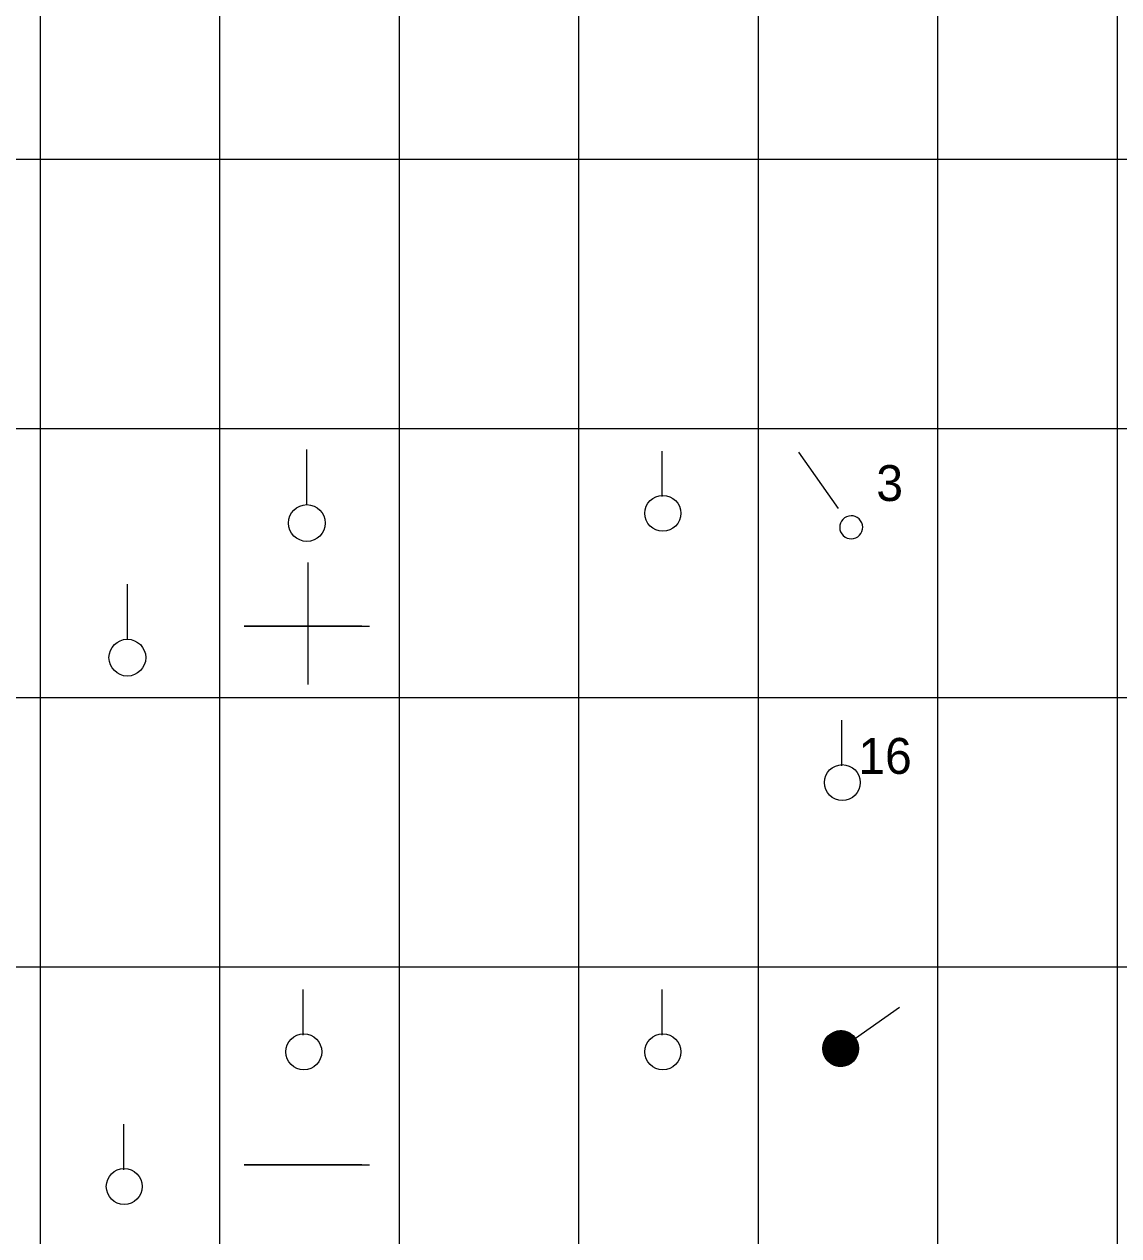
# Model space of a CAD drawing. Extents: x -28 to 822, y 61 to 665.
# Drawn here: x 399.7 to 460.7, y 246.8 to 314.2 of the extents above; entities that cross this region are included whole.
import ezdxf

# ---------------------------------------------------------------- set-up
doc = ezdxf.new("R2010")
doc.units = 0
doc.layers.add('KOLEJIŠTĚ', color=7, linetype='Continuous')

# ---------------------------------------------------------------- blocks, each defined once
blk = doc.blocks.new('_X10')
for p, q in [((370.452, 480.16), (371.464, 481.172)), ((370.452, 480.177), (371.447, 481.172)), ((370.452, 480.195), (371.429, 481.172)), ((370.453, 480.142), (371.482, 481.172)), ((370.453, 480.125), (371.499, 481.171)), ((370.453, 480.214), (371.411, 481.171)), ((370.454, 480.109), (371.515, 481.17)), ((370.454, 480.232), (371.392, 481.17)), ((370.455, 480.092), (371.532, 481.169)), ((370.455, 480.251), (371.373, 481.169)), ((370.457, 480.076), (371.548, 481.167)), ((370.457, 480.271), (371.353, 481.167)), ((370.458, 480.06), (371.564, 481.166)), ((370.459, 480.291), (371.334, 481.165)), ((370.46, 480.044), (371.58, 481.164)), ((370.462, 480.029), (371.596, 481.162)), ((370.462, 480.311), (371.313, 481.162)), ((370.465, 480.013), (371.611, 481.159)), ((370.465, 480.332), (371.293, 481.159)), ((370.467, 479.998), (371.626, 481.157)), ((370.469, 480.353), (371.271, 481.156)), ((370.47, 479.983), (371.641, 481.154)), ((370.473, 479.969), (371.656, 481.151)), ((370.473, 480.375), (371.249, 481.151)), ((370.476, 479.954), (371.67, 481.148)), ((370.478, 480.398), (371.227, 481.146)), ((370.479, 479.94), (371.685, 481.145)), ((370.483, 479.925), (371.699, 481.141)), ((370.484, 480.421), (371.203, 481.141)), ((370.487, 479.911), (371.713, 481.137)), ((370.49, 480.445), (371.179, 481.134)), ((370.491, 479.898), (371.727, 481.134)), ((370.495, 479.884), (371.74, 481.13)), ((370.498, 480.47), (371.154, 481.126)), ((370.499, 479.87), (371.754, 481.125)), ((370.503, 479.857), (371.767, 481.121)), ((370.506, 480.497), (371.127, 481.118)), ((370.507, 479.844), (371.78, 481.117)), ((370.512, 479.831), (371.793, 481.112)), ((370.516, 480.524), (371.1, 481.108)), ((370.517, 479.818), (371.806, 481.107)), ((370.522, 479.805), (371.819, 481.102)), ((370.527, 479.793), (371.832, 481.097)), ((370.528, 480.554), (371.071, 481.096)), ((370.532, 479.78), (371.844, 481.092)), ((370.537, 479.768), (371.856, 481.087)), ((370.541, 480.585), (371.039, 481.083)), ((370.543, 479.756), (371.869, 481.081)), ((370.549, 479.744), (371.881, 481.076)), ((370.554, 479.732), (371.893, 481.07)), ((370.557, 480.618), (371.006, 481.067)), ((370.56, 479.72), (371.904, 481.064)), ((370.566, 479.708), (371.916, 481.058)), ((370.572, 479.697), (371.928, 481.052)), ((370.577, 480.656), (370.968, 481.047)), ((370.579, 479.685), (371.939, 481.046)), ((370.585, 479.674), (371.95, 481.039)), ((370.592, 479.663), (371.961, 481.033)), ((370.598, 479.652), (371.972, 481.026)), ((370.602, 480.698), (370.926, 481.022)), ((370.605, 479.641), (371.983, 481.019)), ((370.612, 479.63), (371.994, 481.012)), ((370.619, 479.619), (372.005, 481.005)), ((370.626, 479.609), (372.015, 480.998)), ((370.633, 479.598), (372.026, 480.991)), ((370.637, 480.751), (370.873, 480.988)), ((370.64, 479.588), (372.036, 480.984)), ((370.648, 479.578), (372.046, 480.976)), ((370.655, 479.568), (372.057, 480.969)), ((370.663, 479.558), (372.067, 480.961)), ((370.671, 479.548), (372.076, 480.953)), ((370.679, 479.538), (372.086, 480.945)), ((370.687, 479.528), (372.096, 480.937)), ((370.695, 479.519), (372.105, 480.929)), ((370.703, 479.509), (372.115, 480.921)), ((370.706, 480.838), (370.786, 480.918)), ((370.712, 479.5), (372.124, 480.913)), ((370.72, 479.491), (372.133, 480.904)), ((370.729, 479.482), (372.142, 480.896)), ((370.737, 479.473), (372.151, 480.887)), ((370.746, 479.464), (372.16, 480.878)), ((370.755, 479.455), (372.169, 480.869)), ((370.764, 479.446), (372.178, 480.86)), ((370.773, 479.438), (372.186, 480.851)), ((370.782, 479.429), (372.195, 480.842)), ((370.792, 479.421), (372.203, 480.832)), ((370.801, 479.413), (372.211, 480.823)), ((370.811, 479.405), (372.219, 480.813)), ((370.821, 479.397), (372.227, 480.804)), ((370.83, 479.389), (372.235, 480.794)), ((370.84, 479.381), (372.243, 480.784)), ((370.85, 479.373), (372.251, 480.774)), ((370.86, 479.366), (372.258, 480.764)), ((370.871, 479.358), (372.266, 480.754)), ((370.881, 479.351), (372.273, 480.743)), ((370.891, 479.344), (372.28, 480.733)), ((370.902, 479.337), (372.287, 480.722)), ((370.913, 479.33), (372.294, 480.711)), ((370.924, 479.323), (372.301, 480.701)), ((370.935, 479.316), (372.308, 480.69)), ((370.946, 479.31), (372.314, 480.678)), ((370.957, 479.303), (372.321, 480.667)), ((370.968, 479.297), (372.327, 480.656)), ((370.98, 479.291), (372.333, 480.645)), ((370.991, 479.285), (372.34, 480.633)), ((371.003, 479.279), (372.346, 480.621)), ((371.015, 479.273), (372.351, 480.609)), ((371.027, 479.267), (372.357, 480.597)), ((371.039, 479.261), (372.363, 480.585)), ((371.051, 479.256), (372.368, 480.573)), ((371.063, 479.251), (372.373, 480.561)), ((371.076, 479.246), (372.379, 480.548)), ((371.089, 479.24), (372.384, 480.536)), ((371.101, 479.236), (372.389, 480.523)), ((371.114, 479.231), (372.393, 480.51)), ((371.127, 479.226), (372.398, 480.497)), ((371.141, 479.222), (372.402, 480.484)), ((371.154, 479.218), (372.407, 480.47)), ((371.167, 479.213), (372.411, 480.457)), ((371.181, 479.209), (372.415, 480.443)), ((371.195, 479.206), (372.419, 480.429)), ((371.209, 479.202), (372.422, 480.415)), ((371.223, 479.199), (372.426, 480.401)), ((371.238, 479.195), (372.429, 480.386)), ((371.252, 479.192), (372.432, 480.372)), ((371.267, 479.189), (372.435, 480.357)), ((371.282, 479.187), (372.438, 480.342)), ((371.297, 479.184), (372.44, 480.327)), ((371.313, 479.182), (372.442, 480.311)), ((371.328, 479.18), (372.444, 480.296)), ((371.344, 479.178), (372.446, 480.28)), ((371.36, 479.176), (372.448, 480.264)), ((371.376, 479.175), (372.449, 480.248)), ((371.393, 479.174), (372.45, 480.231)), ((371.41, 479.173), (372.451, 480.214)), ((371.427, 479.172), (372.452, 480.197)), ((371.444, 479.172), (372.452, 480.18)), ((371.462, 479.172), (372.452, 480.162)), ((371.48, 479.172), (372.452, 480.144)), ((371.498, 479.173), (372.451, 480.126)), ((371.517, 479.174), (372.45, 480.107)), ((371.536, 479.176), (372.449, 480.088)), ((371.556, 479.177), (372.447, 480.068)), ((371.576, 479.18), (372.444, 480.048)), ((371.596, 479.182), (372.442, 480.028)), ((371.617, 479.186), (372.438, 480.007)), ((371.639, 479.19), (372.435, 479.985)), ((371.661, 479.194), (372.43, 479.963)), ((371.684, 479.199), (372.425, 479.941)), ((371.707, 479.205), (372.419, 479.917)), ((371.732, 479.212), (372.412, 479.892)), ((371.757, 479.22), (372.404, 479.867)), ((371.784, 479.229), (372.395, 479.84)), ((371.812, 479.239), (372.385, 479.812)), ((371.841, 479.251), (372.373, 479.783)), ((371.873, 479.265), (372.359, 479.751)), ((371.908, 479.282), (372.342, 479.716)), ((371.946, 479.303), (372.322, 479.678)), ((371.991, 479.329), (372.295, 479.634)), ((372.047, 479.369), (372.256, 479.577))]:
    blk.add_line(p, q)
blk = doc.blocks.new('ZT41')
blk.add_line((5, 10.8), (5, 13.2))
blk.add_circle((5, 10), 0.8)

msp = doc.modelspace()

# ---------------------------------------------------------------- linework, layer by layer
for p, q in [((400.616, 381.738), (400.616, 111.738)), ((410.616, 381.738), (410.616, 111.738)), ((410.616, 381.738), (410.616, 111.738)), ((420.616, 381.738), (420.616, 111.738)), ((430.616, 381.738), (430.616, 111.738)), ((440.616, 381.738), (440.616, 111.738)), ((450.616, 381.738), (450.616, 111.738)), ((460.616, 381.738), (460.616, 111.738)), ((460.616, 381.738), (460.616, 111.738)), ((5.068, 306.738), (540.616, 306.738)), ((5.068, 291.738), (540.616, 291.738)), ((435.278, 287.941), (435.278, 290.474)), ((442.868, 290.42), (445.071, 287.274)), ((415.544, 284.267), (415.544, 277.472)), ((339.087, 276.738), (540.616, 276.738)), ((445.278, 272.941), (445.278, 275.474)), ((5.068, 261.738), (540.616, 261.738)), ((415.278, 257.941), (415.278, 260.474)), ((435.278, 257.941), (435.278, 260.474)), ((446.036, 257.767), (448.486, 259.499)), ((405.278, 250.441), (405.278, 252.974))]:
    msp.add_line(p, q)
for points in [[(412.936, 280.72), (418.537, 280.72), (411.996, 280.72), (418.964, 280.72)], [(412.936, 250.72), (418.537, 250.72), (411.996, 250.72), (418.964, 250.72)]]:
    msp.add_lwpolyline(points)
for centre in [(435.31, 287.005), (445.31, 272.005), (415.31, 257.005), (435.31, 257.005), (445.22, 257.189), (405.31, 249.505)]:
    msp.add_circle(centre, 1)
for start, end in [(35, 215), (215, 35)]:
    msp.add_arc((445.805, 286.226), 0.64, start, end)

# ---------------------------------------------------------------- block references
at = {"rotation": -92.29148628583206}
msp.add_blockref('_X10', (-19.716, 647.543), dxfattribs=at)
at = {"layer": 'KOLEJIŠTĚ', "xscale": 1.2800000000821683, "yscale": 1.2800000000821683}
for p in [(409.082, 273.664), (399.082, 266.164)]:
    msp.add_blockref('ZT41', p, dxfattribs=at)

# ---------------------------------------------------------------- texts
for s, p in [('3', (447.204, 287.69)), ('16', (446.203, 272.49))]:
    msp.add_text(s, height=2).set_placement(p)

doc.saveas('drawing.dxf')
